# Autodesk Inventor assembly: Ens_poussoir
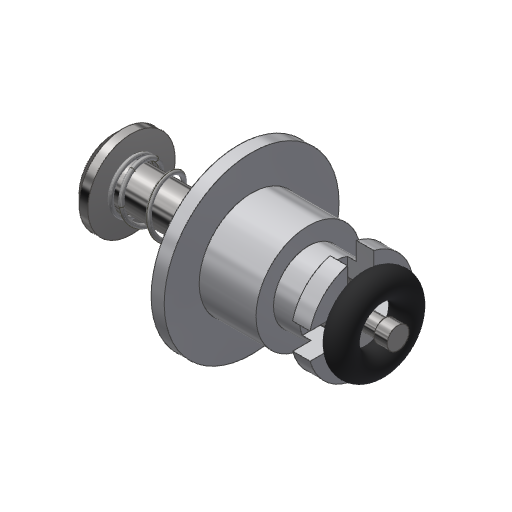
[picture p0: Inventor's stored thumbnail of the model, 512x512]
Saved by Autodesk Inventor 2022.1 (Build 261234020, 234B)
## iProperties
Created: 2018-06
Part Number: Ens_poussoir
Material: Générique
Document SubType Name: Assembly
Designer: Fabian Perrée
Mass: 5.90054 g
Surface Area: 24.3283 cm^2
Volume: 1.88874 cm^3
Density: 3.12406 g/cm^3
Author: Fabian Perrée
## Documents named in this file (5)
- C:\Users\fabia\Mon Drive\01_Giup\01_Clients\07_ENI\Manuscrit\Fichiers_exercice\Chapitre_06\Exercice_jeu_de_composant_en_contact\Composants\Ens_poussoir\Ens_poussoir.iam
- C:\Users\fabia\Mon Drive\01_Giup\01_Clients\07_ENI\Manuscrit\Fichiers_exercice\Chapitre_06\Exercice_jeu_de_composant_en_contact\Composants\Ens_poussoir\Composants\Guide.ipt
- C:\Users\fabia\Mon Drive\01_Giup\01_Clients\07_ENI\Manuscrit\Fichiers_exercice\Chapitre_06\Exercice_jeu_de_composant_en_contact\Composants\Ens_poussoir\Composants\Poussoir.ipt
- C:\Users\fabia\Mon Drive\01_Giup\01_Clients\07_ENI\Manuscrit\Fichiers_exercice\Chapitre_06\Exercice_jeu_de_composant_en_contact\Composants\Ens_poussoir\Composants\Joint.ipt
- C:\Users\fabia\Mon Drive\01_Giup\01_Clients\07_ENI\Manuscrit\Fichiers_exercice\Chapitre_06\Exercice_chapitre_06\Composants\Ressort de compression12.ipt
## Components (4 placed, 4 different names)
1. Guide:1 — Tangente:2, Placage:2
2. Poussoir:1 — Placage:1, Placage:2, Placage:3, Placage:4
3. Joint:1 — Tangente:2, Placage:1
4. Ressort de compression1:1 — Placage:3, Placage:4
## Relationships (5: Mate 4, Tangent 1)
- Tangente:2: Guide:1 ↔ Joint:1
- Placage:1 [Mate]: Poussoir:1 ↔ Joint:1
- Placage:2 [Mate]: Guide:1 ↔ Poussoir:1
- Placage:3 [Mate]: Poussoir:1 ↔ Ressort de compression1:1
- Placage:4 [Mate]: Poussoir:1 ↔ Ressort de compression1:1
